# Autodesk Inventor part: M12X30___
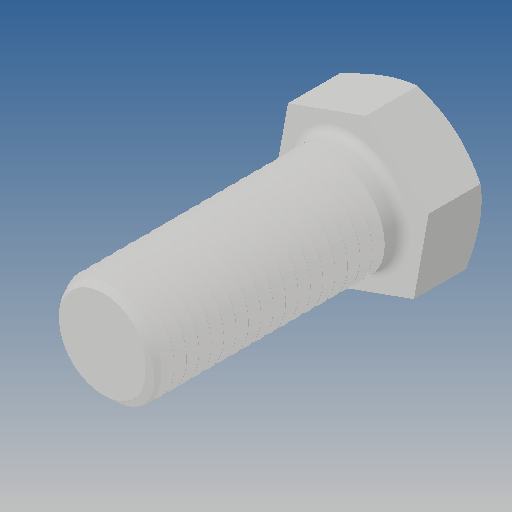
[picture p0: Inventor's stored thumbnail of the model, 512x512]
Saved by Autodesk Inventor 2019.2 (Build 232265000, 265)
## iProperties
Created: 2010-06
Part Number: M12X30___
Material: Ogólny
Document SubType Name: Modeling
Designer: CADENGINEERING4
Density: 1 g/cm^3
Appearance: Domyślna
Author: CADENGINEERING4
Revision Number: ANY
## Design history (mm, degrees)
feature "NONE"
node "Bryła1"
